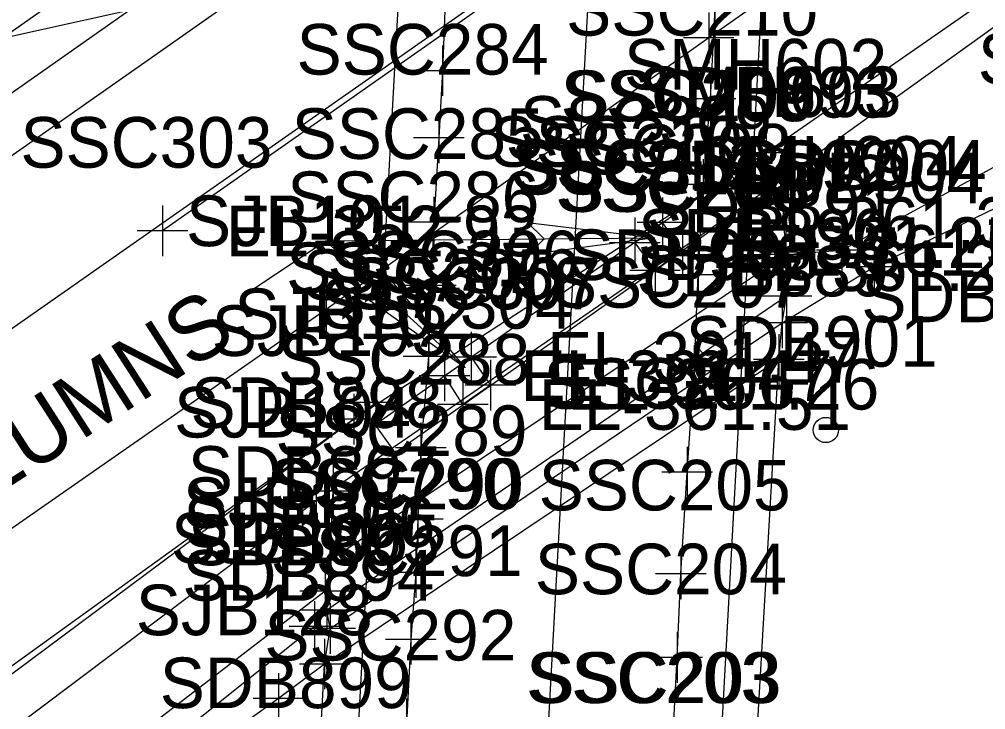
# Model space of a CAD drawing. Extents: x 941041 to 969446, y 397014 to 416764.
# Drawn here: x 951822 to 951898.4, y 403134.3 to 403188.8 of the extents above; entities that cross this region are included whole.
import ezdxf

# ---------------------------------------------------------------- set-up
doc = ezdxf.new("R2010")
doc.units = 0
for name, color, linetype in [('SURVEY - CENTERLINE - Preliminary', 7, 'Continuous'), ('SURVEY - DRAINAGE - Area Shapes', 7, 'Continuous'), ('SURVEY - DRAINAGE - Bridge Hydraulic Data - Points - Locators', 7, 'Continuous'), ('SURVEY - DRAINAGE - Bridge Hydraulic Data - Points - Numbers', 7, 'Continuous'), ('SURVEY - DRAINAGE - Bridge Hydraulic Data with Text', 7, 'Continuous'), ('SURVEY - DRAINAGE - Bridges', 7, 'Continuous'), ('SURVEY - DRAINAGE - Pipes and Culverts', 7, 'Continuous'), ('SURVEY - DTM - Breaklines', 7, 'Continuous'), ('SURVEY - DTM - Breaklines - Points - Locators', 7, 'Continuous'), ('SURVEY - DTM - Breaklines - Points - Numbers', 7, 'Continuous'), ('SURVEY - DTM - Spot Points - Locators', 7, 'Continuous'), ('SURVEY - DTM - Spot Points - Point Numbers', 7, 'Continuous'), ('SURVEY - NON-TRANSPORTATION - Features', 7, 'Continuous'), ('SURVEY - NON-TRANSPORTATION - Features - Points - Elevations', 7, 'Continuous'), ('SURVEY - NON-TRANSPORTATION - Features - Points - Locators', 7, 'Continuous'), ('SURVEY - NON-TRANSPORTATION - Features - Points - Numbers', 7, 'Continuous'), ('SURVEY - NON-TRANSPORTATION - Features Text', 7, 'Continuous'), ('SURVEY - ROADSIDE BARRIERS - Points - Locators', 7, 'Continuous'), ('SURVEY - ROADSIDE BARRIERS - Points - Numbers', 7, 'Continuous'), ('SURVEY - ROADSIDE BARRIERS with Text', 7, 'Continuous'), ('SURVEY - TRAFFIC CONTROL - Pavement Marking - Points - Elevations', 7, 'Continuous'), ('SURVEY - TRAFFIC CONTROL - Pavement Marking - Points - Locators', 7, 'Continuous'), ('SURVEY - TRAFFIC CONTROL - Pavement Marking - Points - Numbers', 7, 'Continuous'), ('SURVEY - TRAFFIC CONTROL - Pavement Marking with Text', 7, 'Continuous'), ('SURVEY - TRANSPORTATION - Features', 7, 'Continuous'), ('SURVEY - TRANSPORTATION - Features - Points - Locators', 7, 'Continuous'), ('SURVEY - TRANSPORTATION - Features - Points - Numbers', 7, 'Continuous'), ('SURVEY - TRANSPORTATION - Roads', 7, 'Continuous'), ('SURVEY - TRANSPORTATION - Roads - Points - Locators', 7, 'Continuous'), ('SURVEY - TRANSPORTATION - Roads - Points - Numbers', 7, 'Continuous')]:
    doc.layers.add(name, color=color, linetype=linetype)

msp = doc.modelspace()

# ---------------------------------------------------------------- linework, layer by layer
at = {"layer": 'SURVEY - CENTERLINE - Preliminary'}
msp.add_line((951818.981, 402312.968), (951929.937, 404341.516), dxfattribs=at)
at = {"layer": 'SURVEY - DRAINAGE - Area Shapes'}
msp.add_lwpolyline([(950765.728, 402528.114), (950855.069, 402487.284), (951056.086, 402625.135), (951609.085, 403015.699), (952524.782, 403657.049), (952475.834, 403724.713)], dxfattribs=at)
at = {"layer": 'SURVEY - DRAINAGE - Bridge Hydraulic Data - Points - Locators'}
for p, q in [((951876.976, 403191.199), (951876.976, 403187.199)), ((951855.453, 403186.776), (951855.453, 403182.776)), ((951857.453, 403184.776), (951853.453, 403184.776)), ((951876.633, 403184.55), (951876.633, 403180.55)), ((951878.633, 403182.55), (951874.633, 403182.55)), ((951855.154, 403181.466), (951855.154, 403177.466)), ((951857.154, 403179.466), (951853.154, 403179.466)), ((951876.05, 403177.784), (951876.05, 403173.784)), ((951878.05, 403175.784), (951874.05, 403175.784)), ((951854.766, 403174.803), (951854.766, 403170.803)), ((951856.766, 403172.803), (951852.766, 403172.803)), ((951875.66, 403170.632), (951875.66, 403166.632)), ((951854.527, 403169.807), (951854.527, 403165.807)), ((951877.66, 403168.632), (951873.66, 403168.632)), ((951856.527, 403167.807), (951852.527, 403167.807)), ((951854.332, 403164.197), (951854.332, 403160.197)), ((951875.34, 403163.047), (951875.34, 403159.047)), ((951856.332, 403162.197), (951852.332, 403162.197)), ((951877.34, 403161.047), (951873.34, 403161.047)), ((951853.737, 403156.969), (951853.737, 403152.969)), ((951855.737, 403154.969), (951851.737, 403154.969)), ((951874.781, 403155.054), (951874.781, 403151.054)), ((951876.781, 403153.054), (951872.781, 403153.054)), ((951853.501, 403151.322), (951853.501, 403147.322)), ((951855.501, 403149.322), (951851.501, 403149.322)), ((951853.344, 403147.122), (951853.344, 403143.122)), ((951874.289, 403147.021), (951874.289, 403143.021)), ((951855.344, 403145.122), (951851.344, 403145.122)), ((951876.289, 403145.021), (951872.289, 403145.021)), ((951852.956, 403141.834), (951852.956, 403137.834)), ((951873.991, 403140.396), (951873.991, 403136.396)), ((951854.956, 403139.834), (951850.956, 403139.834)), ((951875.991, 403138.396), (951871.991, 403138.396)), ((951852.61, 403135.163), (951852.61, 403131.163))]:
    msp.add_line(p, q, dxfattribs=at)
at = {"layer": 'SURVEY - DRAINAGE - Bridge Hydraulic Data with Text'}
for points in [[(951857.271, 403219.255), (951857.09, 403214.353), (951856.747, 403208.521), (951856.472, 403203.599), (951856.176, 403198.101), (951855.721, 403191.568), (951855.453, 403184.776), (951855.154, 403179.466), (951854.766, 403172.803), (951854.527, 403167.807), (951854.332, 403162.197), (951853.737, 403154.969), (951853.501, 403149.322), (951853.344, 403145.122), (951852.956, 403139.834), (951852.61, 403133.163), (951852.185, 403125.153), (951851.723, 403118.23), (951851.344, 403110.56), (951851.121, 403105.268), (951850.79, 403098.495)], [(951872.717, 403114.376), (951873.105, 403121.528), (951873.551, 403129.814), (951873.991, 403138.396), (951874.289, 403145.021), (951874.781, 403153.054), (951875.34, 403161.047), (951875.66, 403168.632), (951876.05, 403175.784), (951876.633, 403182.55), (951876.976, 403189.199), (951877.02, 403194.908), (951877.232, 403199.971), (951877.862, 403206.534), (951877.965, 403211.834), (951878.272, 403218.86)]]:
    msp.add_lwpolyline(points, dxfattribs=at)
at = {"layer": 'SURVEY - DRAINAGE - Bridges'}
msp.add_lwpolyline([(951862.723, 403386.103), (951892.52, 403406.808), (951876.389, 403112.43), (951846.539, 403091.795), (951862.715, 403385.151), (951862.723, 403386.103)], dxfattribs=at)
at = {"layer": 'SURVEY - DRAINAGE - Pipes and Culverts'}
msp.add_lwpolyline([(951575.842, 403043.756), (951765.833, 403175.232), (951951.923, 403216.392)], dxfattribs=at)
at = {"layer": 'SURVEY - DTM - Breaklines'}
for points in [[(951846.556, 403146.1), (951882.591, 403170.257), (951887.025, 403170.601), (951935.217, 403196.935), (951981.805, 403226.137), (952031.67, 403259.484), (952078.257, 403295.415), (952132.188, 403332.309), (952180.722, 403366.295), (952219.859, 403395.407), (952263.528, 403428.198), (952276.957, 403440.295)], [(951846.563, 403140.687), (951882.308, 403164.849), (951889.577, 403169.287), (951909.007, 403178.717), (951933.139, 403194.942), (951952.284, 403206.688)], [(951879.65, 403120.66), (951882.04, 403161.944), (951882.308, 403164.849), (951882.641, 403166.968), (951882.591, 403170.257), (951882.266, 403176.071)], [(951882.641, 403166.968), (951846.315, 403142.135), (951845.336, 403140.85), (951800.524, 403105.062), (951758.247, 403071.505), (951712.6, 403041.512), (951668.468, 403010.93), (951623.099, 402980.198), (951576.624, 402946.494), (951535.079, 402916.864), (951489.079, 402884.215), (951442.455, 402851.9), (951396.059, 402820.245), (951353.638, 402790.695), (951305.865, 402756.614)], [(951882.04, 403161.944), (951846.133, 403137.884), (951842.492, 403135.158), (951819.493, 403118.63), (951804.312, 403100.556), (951797.51, 403082.912), (951802.835, 403059.09), (951802.811, 403022.015), (951804.054, 402974.849), (951803.852, 402952.87), (951795.18, 402940.67), (951774.197, 402924.202), (951748.94, 402915.058), (951703.154, 402898.472), (951666.256, 402887.337), (951618.016, 402879.462), (951581.51, 402871.514), (951533.199, 402851.746), (951496.154, 402840.06)], [(951843.842, 403095.625), (951846.133, 403137.884), (951846.563, 403140.687), (951846.315, 403142.135), (951846.556, 403146.1), (951846.816, 403151.539)], [(951846.167, 403143.63), (951798.245, 403106.853), (951755.363, 403076.106), (951709.515, 403045.74), (951665.692, 403013.775), (951621.546, 402983.273), (951574.757, 402950.88), (951533.182, 402922.12), (951486.759, 402887.775), (951441.321, 402857.796), (951393.846, 402824.12), (951350.676, 402794.892), (951304.418, 402761.093), (951261.648, 402730.038), (951245.944, 402719.494)]]:
    msp.add_lwpolyline(points, dxfattribs=at)
at = {"layer": 'SURVEY - DTM - Breaklines - Points - Locators'}
for p, q in [((951887.025, 403172.601), (951887.025, 403168.601)), ((951889.577, 403171.287), (951889.577, 403167.287)), ((951889.025, 403170.601), (951885.025, 403170.601)), ((951891.577, 403169.287), (951887.577, 403169.287)), ((951846.167, 403145.63), (951846.167, 403141.63)), ((951848.167, 403143.63), (951844.167, 403143.63)), ((951845.336, 403142.85), (951845.336, 403138.85)), ((951847.336, 403140.85), (951843.336, 403140.85)), ((951842.492, 403137.158), (951842.492, 403133.158)), ((951844.492, 403135.158), (951840.492, 403135.158))]:
    msp.add_line(p, q, dxfattribs=at)
at = {"layer": 'SURVEY - DTM - Spot Points - Locators'}
for centre in [(951876.647, 403163.226), (951885.752, 403156.379)]:
    msp.add_circle(centre, 1, dxfattribs=at)
at = {"layer": 'SURVEY - NON-TRANSPORTATION - Features'}
for p, q in [((951850.126, 403156.815), (951878.255, 403176.579)), ((951851.706, 403154.613), (951879.77, 403174.331))]:
    msp.add_line(p, q, dxfattribs=at)
for points in [[(951874.413, 403170.567), (951872.827, 403172.765), (951870.652, 403171.182), (951872.248, 403168.991), (951874.413, 403170.567)], [(951857.061, 403158.391), (951855.601, 403160.662), (951857.72, 403162.125), (951859.242, 403159.919), (951857.061, 403158.391)]]:
    msp.add_lwpolyline(points, dxfattribs=at)
at = {"layer": 'SURVEY - NON-TRANSPORTATION - Features - Points - Locators'}
for p, q in [((951882.266, 403178.071), (951882.266, 403174.071)), ((951884.266, 403176.071), (951880.266, 403176.071)), ((951872.827, 403174.765), (951872.827, 403170.765)), ((951870.652, 403173.182), (951870.652, 403169.182)), ((951874.827, 403172.765), (951870.827, 403172.765)), ((951874.413, 403172.567), (951874.413, 403168.567)), ((951882.591, 403172.257), (951882.591, 403168.257)), ((951872.652, 403171.182), (951868.652, 403171.182)), ((951872.248, 403170.991), (951872.248, 403166.991)), ((951876.413, 403170.567), (951872.413, 403170.567)), ((951884.591, 403170.257), (951880.591, 403170.257)), ((951874.248, 403168.991), (951870.248, 403168.991)), ((951882.641, 403168.968), (951882.641, 403164.968)), ((951884.641, 403166.968), (951880.641, 403166.968)), ((951882.308, 403166.849), (951882.308, 403162.849)), ((951884.308, 403164.849), (951880.308, 403164.849)), ((951857.72, 403164.125), (951857.72, 403160.125)), ((951882.04, 403163.944), (951882.04, 403159.944)), ((951882.04, 403163.944), (951882.04, 403159.944)), ((951855.601, 403162.662), (951855.601, 403158.662)), ((951859.72, 403162.125), (951855.72, 403162.125)), ((951859.242, 403161.919), (951859.242, 403157.919)), ((951884.04, 403161.944), (951880.04, 403161.944)), ((951884.04, 403161.944), (951880.04, 403161.944)), ((951857.601, 403160.662), (951853.601, 403160.662)), ((951857.061, 403160.391), (951857.061, 403156.391)), ((951861.242, 403159.919), (951857.242, 403159.919)), ((951859.061, 403158.391), (951855.061, 403158.391)), ((951846.816, 403153.539), (951846.816, 403149.539)), ((951848.816, 403151.539), (951844.816, 403151.539)), ((951846.556, 403148.1), (951846.556, 403144.1)), ((951848.556, 403146.1), (951844.556, 403146.1)), ((951846.315, 403144.135), (951846.315, 403140.135)), ((951846.563, 403142.687), (951846.563, 403138.687)), ((951848.315, 403142.135), (951844.315, 403142.135)), ((951848.563, 403140.687), (951844.563, 403140.687)), ((951846.133, 403139.884), (951846.133, 403135.884)), ((951848.133, 403137.884), (951844.133, 403137.884))]:
    msp.add_line(p, q, dxfattribs=at)
at = {"layer": 'SURVEY - NON-TRANSPORTATION - Features Text'}
for p, q in [((951879.77, 403174.331), (951878.255, 403176.579)), ((951839.523, 403166.888), (951846.193, 403171.334)), ((951846.193, 403171.334), (951872.242, 403171.562)), ((951846.193, 403171.334), (951857.234, 403161.279)), ((951851.706, 403154.613), (951850.124, 403156.814))]:
    msp.add_line(p, q, dxfattribs=at)
for points in [[(951872.239, 403171.562), (951862.2, 403170.224), (951863.489, 403171.485), (951862.178, 403172.774)], [(951857.234, 403161.279), (951848.962, 403167.122), (951850.765, 403167.17), (951850.679, 403169.007)]]:
    msp.add_lwpolyline(points, close=True, dxfattribs=at)
for points in [[(951872.239, 403171.562), (951862.2, 403170.224), (951863.489, 403171.485), (951862.178, 403172.774), (951872.239, 403171.562)], [(951857.234, 403161.279), (951848.962, 403167.122), (951850.765, 403167.17), (951850.679, 403169.007), (951857.234, 403161.279)]]:
    msp.add_lwpolyline(points, dxfattribs=at)
at = {"layer": 'SURVEY - ROADSIDE BARRIERS - Points - Locators'}
for p, q in [((951850.238, 403160.562), (951850.238, 403156.562)), ((951852.238, 403158.562), (951848.238, 403158.562))]:
    msp.add_line(p, q, dxfattribs=at)
at = {"layer": 'SURVEY - ROADSIDE BARRIERS with Text'}
msp.add_line((951850.238, 403158.562), (951793.028, 403115.984), dxfattribs=at)
at = {"layer": 'SURVEY - TRAFFIC CONTROL - Pavement Marking - Points - Locators'}
for p, q in [((951833.327, 403174.111), (951833.327, 403170.111)), ((951835.327, 403172.111), (951831.327, 403172.111))]:
    msp.add_line(p, q, dxfattribs=at)
at = {"layer": 'SURVEY - TRAFFIC CONTROL - Pavement Marking with Text'}
msp.add_lwpolyline([(951902.139, 403220.442), (951869.821, 403197.714), (951833.327, 403172.111)], dxfattribs=at)
at = {"layer": 'SURVEY - TRANSPORTATION - Features'}
for points in [[(952356.312, 403508.85), (952319.541, 403482.532), (952271.199, 403449.462), (952218.017, 403412.102), (952168.512, 403377.19), (952118.637, 403342.503), (952070.407, 403308.532), (952018.599, 403272.328), (951969.849, 403238.114), (951920.07, 403203.331), (951882.159, 403176.106), (951845.469, 403150.786)], [(951856.725, 403212.679), (951764.5, 403147.887), (951717.584, 403116.599), (951672.858, 403085.818), (951622.894, 403050.602), (951589.608, 403026.667), (951541.468, 402992.462), (951493.879, 402958.875), (951445.623, 402924.242), (951399.068, 402891.811), (951350.716, 402858.881), (951303.21, 402826.014), (951256.163, 402792.288), (951210.707, 402760.72), (951159.213, 402724.853), (951109.634, 402690.184), (951062.081, 402656.916), (951014.837, 402623.152), (950965.727, 402588.73), (950917.417, 402555.241)], [(951845.469, 403150.786), (951794.852, 403112.741), (951750.755, 403081.678), (951706.797, 403050.619), (951661.084, 403019.604), (951617.487, 402989.414), (951570.551, 402956.656), (951529.619, 402928.23), (951481.561, 402894.72), (951437.37, 402863.285), (951389.549, 402829.634), (951347.657, 402799.301), (951299.968, 402764.935), (951259.616, 402733.329), (951238.853, 402716.854), (951240.37, 402714.071), (951266.379, 402722.325)]]:
    msp.add_lwpolyline(points, dxfattribs=at)
at = {"layer": 'SURVEY - TRANSPORTATION - Features - Points - Locators'}
for p, q in [((951882.159, 403178.106), (951882.159, 403174.106)), ((951884.159, 403176.106), (951880.159, 403176.106)), ((951845.469, 403152.786), (951845.469, 403148.786)), ((951847.469, 403150.786), (951843.469, 403150.786))]:
    msp.add_line(p, q, dxfattribs=at)
at = {"layer": 'SURVEY - TRANSPORTATION - Roads'}
msp.add_line((951856.936, 403208.015), (951806.036, 403172.2), dxfattribs=at)
for points in [[(952447.343, 403587.642), (952403.738, 403556.932), (952357.947, 403524.797), (952311.77, 403492.647), (952264.087, 403459.223), (952211.175, 403421.938), (952159.193, 403385.581), (952111.449, 403351.908), (952063.962, 403319.032), (952011.559, 403282.128), (951962.38, 403247.784), (951912.176, 403212.481), (951876.491, 403187.383), (951846.257, 403165.908)], [(952363.655, 403516.112), (952318.604, 403484.638), (952270.504, 403450.603), (952217.028, 403413.11), (952165.818, 403377.482), (952117.663, 403343.679), (952069.643, 403309.921), (952017.589, 403273.336), (951968.614, 403239.234), (951919.386, 403204.954), (951881.031, 403178.287), (951848.447, 403157.23)], [(951858.055, 403203.771), (951808.392, 403168.939), (951765.125, 403138.615), (951722.924, 403108.999), (951677.222, 403076.945), (951628.721, 403042.912), (951593.383, 403018.088), (951546.628, 402985.285), (951497.777, 402951.073), (951450.208, 402917.781), (951402.734, 402884.45), (951356.412, 402851.908), (951307.814, 402817.827), (951261.245, 402785.239), (951215.146, 402752.961), (951165.073, 402717.743), (951114.376, 402682.191), (951068.412, 402650.051), (951019.303, 402615.593), (950970.868, 402581.821), (950921.094, 402547.351)], [(951846.257, 403165.908), (951785.945, 403123.906), (951742.658, 403093.304), (951698.877, 403062.609), (951653.783, 403030.955), (951609.85, 403000.508), (951563.273, 402967.881), (951522.396, 402938.865), (951473.596, 402904.825), (951429.781, 402874.167), (951382.72, 402841.035), (951339.818, 402810.624), (951292.163, 402777.264), (951248.301, 402746.752), (951245.27, 402744.513), (951200.706, 402713.096), (951156.139, 402681.852), (951111.63, 402650.983), (951070.06, 402621.379)], [(951848.447, 403157.23), (951792.216, 403116.662), (951747.916, 403084.661), (951704.821, 403054.15), (951659.858, 403022.582), (951615.996, 402991.969), (951569.239, 402959.229), (951528.217, 402930.378), (951479.576, 402896.458), (951435.745, 402865.603), (951388.119, 402832.249), (951346.184, 402801.692), (951298.049, 402767.118), (951257.181, 402736.22), (951253.471, 402733.27), (951213.305, 402701.789), (951214.381, 402699.385), (951243.595, 402710.942), (951265.417, 402718.748)]]:
    msp.add_lwpolyline(points, dxfattribs=at)
at = {"layer": 'SURVEY - TRANSPORTATION - Roads - Points - Locators'}
for p, q in [((951876.491, 403189.383), (951876.491, 403185.383)), ((951878.491, 403187.383), (951874.491, 403187.383)), ((951881.031, 403180.287), (951881.031, 403176.287)), ((951883.031, 403178.287), (951879.031, 403178.287)), ((951846.257, 403167.908), (951846.257, 403163.908)), ((951848.257, 403165.908), (951844.257, 403165.908)), ((951848.447, 403159.23), (951848.447, 403155.23)), ((951850.447, 403157.23), (951846.447, 403157.23))]:
    msp.add_line(p, q, dxfattribs=at)

# ---------------------------------------------------------------- texts
at = {"layer": 'SURVEY - DRAINAGE - Bridge Hydraulic Data - Points - Numbers'}
for s, p in [('SSC210', (951865.22, 403187.55)), ('SSC284', (951843.914, 403184.466)), ('SSC209', (951864.795, 403180.784)), ('SSC209', (951865.072, 403180.788)), ('SSC285', (951843.526, 403177.803)), ('SSC208', (951864.373, 403173.632)), ('SSC208', (951864.651, 403173.62)), ('SSC286', (951843.177, 403172.807)), ('SSC287', (951843.092, 403167.197)), ('SSC207', (951864.1, 403166.047)), ('SSC288', (951842.45, 403159.969)), ('SSC206', (951863.431, 403158.054)), ('SSC289', (951842.246, 403154.322)), ('SSC290', (951841.638, 403150.109)), ('SSC290', (951841.931, 403150.122)), ('SSC205', (951863.049, 403150.021)), ('SSC291', (951841.874, 403144.834)), ('SSC204', (951862.751, 403143.396)), ('SSC292', (951841.37, 403138.163)), ('SSC203', (951862.063, 403134.802)), ('SSC203', (951862.311, 403134.814))]:
    msp.add_text(s, height=4, dxfattribs=at).set_placement(p)
at = {"layer": 'SURVEY - DTM - Breaklines - Points - Numbers'}
for s, p in [('SDB905', (951897.767, 403183.717)), ('SMH604', (951875.785, 403175.601)), ('SDB904', (951878.535, 403175.298)), ('SDB904', (951878.337, 403174.287)), ('SJB105', (951834.927, 403148.63)), ('SJB106', (951833.986, 403145.85)), ('SJB128', (951831.205, 403140.158))]:
    msp.add_text(s, height=4, dxfattribs=at).set_placement(p)
at = {"layer": 'SURVEY - DTM - Spot Points - Point Numbers'}
for s, p in [('SDB903', (951865.407, 403168.226)), ('SDB902', (951888.559, 403164.9)), ('SDB901', (951874.67, 403161.379)), ('SDB899', (951833.1, 403134.397))]:
    msp.add_text(s, height=4, dxfattribs=at).set_placement(p)
at = {"layer": 'SURVEY - NON-TRANSPORTATION - Features - Points - Elevations'}
for s, p in [('EL-361.31', (951878.827, 403170.765)), ('EL-361.25', (951876.652, 403169.182)), ('EL-361.26', (951880.413, 403168.567)), ('EL-361.20', (951877.923, 403167.36)), ('EL-361.47', (951863.72, 403160.125)), ('EL-361.47', (951861.601, 403158.662)), ('EL-361.26', (951865.287, 403157.997)), ('EL-361.51', (951863.061, 403156.391))]:
    msp.add_text(s, height=4, dxfattribs=at).set_placement(p)
at = {"layer": 'SURVEY - NON-TRANSPORTATION - Features - Points - Numbers'}
for s, p in [('SDB893', (951871.026, 403181.071)), ('SSC309', (951861.572, 403178.765)), ('SSC310', (951859.239, 403177.182)), ('SSC308', (951863.126, 403176.567)), ('SSC311', (951860.841, 403175.36)), ('SDB892', (951871.351, 403175.257)), ('SSC311', (951861.166, 403174.991)), ('SDB891', (951871.559, 403171.968)), ('SDB890', (951870.895, 403169.849)), ('SSC306', (951846.37, 403168.125)), ('SDB889', (951870.785, 403166.944)), ('SDB889', (951870.785, 403166.944)), ('SSC305', (951844.361, 403166.662)), ('SSC307', (951848.003, 403165.919)), ('SSC307', (951848.047, 403165.997)), ('SSC304', (951845.821, 403164.391)), ('SDB898', (951835.53, 403156.539)), ('SDB897', (951835.316, 403151.1)), ('SDB896', (951834.965, 403147.135)), ('SDB895', (951835.323, 403145.687)), ('SDB894', (951834.893, 403142.884))]:
    msp.add_text(s, height=4, dxfattribs=at).set_placement(p)
at = {"layer": 'SURVEY - NON-TRANSPORTATION - Features Text'}
msp.add_text('COLUMNS', height=4.998, rotation=32.78428, dxfattribs=at).set_placement((951811.233, 403145.443))
at = {"layer": 'SURVEY - ROADSIDE BARRIERS - Points - Numbers'}
msp.add_text('SJB102', height=4, dxfattribs=at).set_placement((951838.998, 403163.562))
at = {"layer": 'SURVEY - TRAFFIC CONTROL - Pavement Marking - Points - Elevations'}
msp.add_text('EL-352.93', height=4, dxfattribs=at).set_placement((951838.327, 403170.111))
at = {"layer": 'SURVEY - TRAFFIC CONTROL - Pavement Marking - Points - Numbers'}
msp.add_text('SSC303', height=4, dxfattribs=at).set_placement((951822.087, 403177.111))
at = {"layer": 'SURVEY - TRANSPORTATION - Features - Points - Numbers'}
for s, p in [('SMH603', (951870.919, 403181.106)), ('SJB104', (951834.229, 403155.786))]:
    msp.add_text(s, height=4, dxfattribs=at).set_placement(p)
at = {"layer": 'SURVEY - TRANSPORTATION - Roads - Points - Numbers'}
for s, p in [('SMH602', (951869.791, 403183.287)), ('SJB101', (951835.175, 403170.908)), ('SJB103', (951837.207, 403162.23))]:
    msp.add_text(s, height=4, dxfattribs=at).set_placement(p)

doc.saveas('drawing.dxf')
